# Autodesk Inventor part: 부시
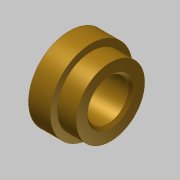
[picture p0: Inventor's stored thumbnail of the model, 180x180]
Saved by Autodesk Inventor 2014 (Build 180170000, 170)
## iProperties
Created: 2016-05
Part Number: 부시
Document SubType Name: Modeling
Designer: mduedu
Density: 7.86 g/cm^3
Material: 강철, 연강
Appearance: Brass - Satin
Author: mduedu
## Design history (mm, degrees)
sketch "스케치1"
  geometry: L1 (0, 0)-(15, 0); L2 (0, 7.5)-(15, 7.5); L3 (15, 7.5)-(15, 12.5); L4 (15, 12.5)-(8, 12.5); L5 (8, 12.5)-(8, 15); L6 (8, 15)-(0, 15); L7 (0, 15)-(0, 7.5)
  constraints: 14 end point, 4 parallel, 2 vertical alignment, 1 horizontal, 1 perpendicular, 1 vertical
  dimensions: "d0" = 15 distance of L1.start L1.end; "d1" = 15 diameter of L2 L1; "d2" = 25 diameter of L4 L1; "d3" = 8 distance of L5.end L6.end; "d4" = 30 diameter of L6 L1
revolve "회전1" sketch "스케치1" stored, may be unused: angle "d5" = 90 deg
chamfer "모따기1" distance "d6" = 1; stored, may be unused: second distance "d7" = 2, angle "d8" = 45 deg
node "솔리드1"
